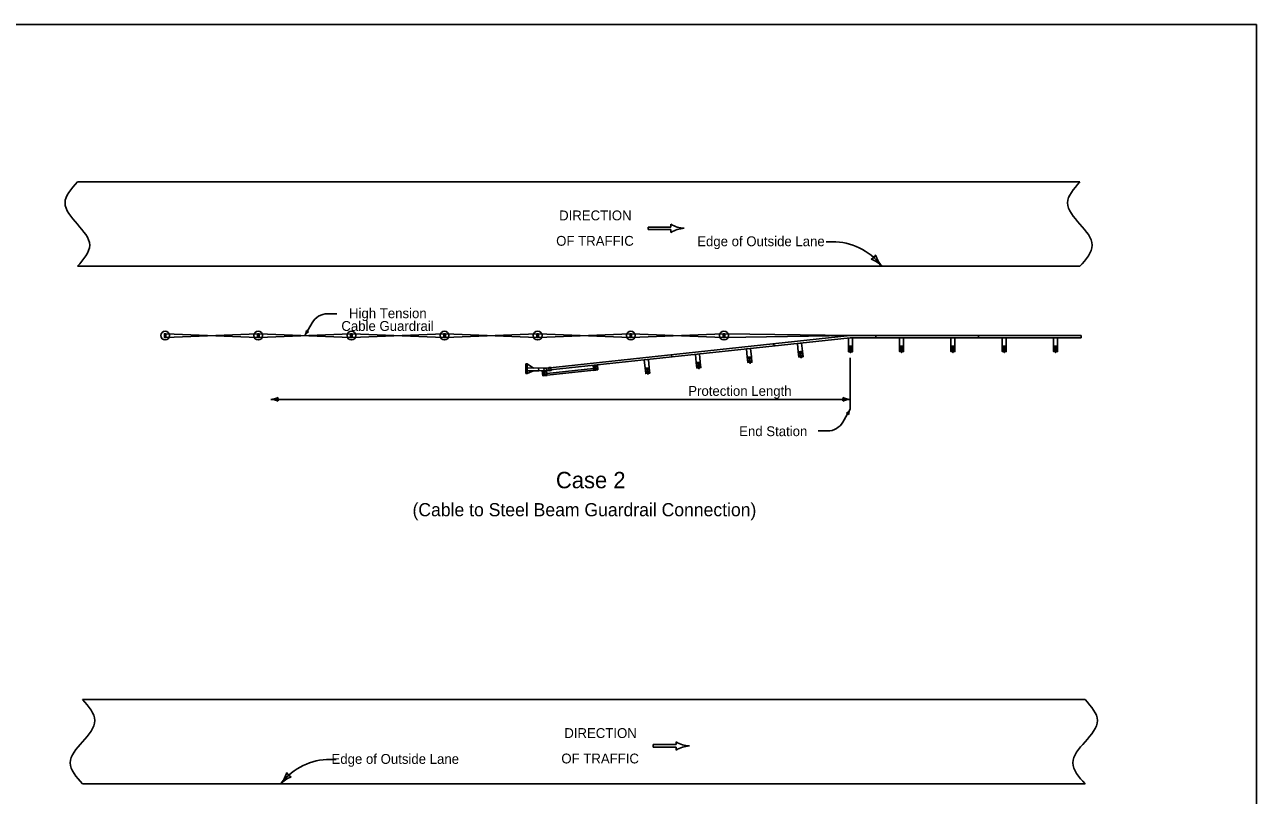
# Model space of a CAD drawing. Extents: x 10133 to 81668, y 7924 to 11018.
# Drawn here: x 22568 to 24068, y 9005 to 9944 of the extents above; entities that cross this region are included whole.
import ezdxf

# ---------------------------------------------------------------- set-up
doc = ezdxf.new("R2010")
doc.units = 0
for name, color, linetype in [('dsnCellElements', 7, 'Continuous'), ('DsnShtRevisedText', 7, 'Continuous'), ('dsnStdDimension', 7, 'Continuous'), ('Level 2', 7, 'Continuous'), ('Level 8', 7, 'Continuous'), ('SheetBorder', 7, 'Continuous')]:
    doc.layers.add(name, color=color, linetype=linetype)

msp = doc.modelspace()

# ---------------------------------------------------------------- linework, layer by layer
at = {"layer": 'dsnCellElements'}
for p, q in [((22851.5, 9562.9), (22740, 9567.4)), ((22851.5, 9567.4), (22740, 9562.9)), ((22964.9, 9562.9), (22853.4, 9567.4)), ((22964.9, 9567.4), (22853.4, 9562.9)), ((23078.3, 9562.9), (22966.8, 9567.4)), ((23078.3, 9567.4), (22966.8, 9562.9)), ((23191.7, 9562.9), (23080.2, 9567.4)), ((23191.7, 9567.4), (23080.2, 9562.9)), ((23305.1, 9562.9), (23193.6, 9567.4)), ((23305.1, 9567.4), (23193.6, 9562.9)), ((23418.5, 9562.9), (23307, 9567.4)), ((23418.5, 9567.4), (23307, 9562.9)), ((23420.4, 9567.5), (23573.1, 9565.2)), ((23420.4, 9562.9), (23573.1, 9565.2))]:
    msp.add_line(p, q, dxfattribs=at)
for points in [[(22740, 9567.4), (22740, 9562.9), (22738.1, 9562.9), (22738.1, 9567.4)], [(22853.4, 9567.4), (22853.4, 9562.9), (22851.5, 9562.9), (22851.5, 9567.4)], [(22853.4, 9567.4), (22853.4, 9562.9), (22851.5, 9562.9), (22851.5, 9567.4)], [(22966.8, 9567.4), (22966.8, 9562.9), (22964.9, 9562.9), (22964.9, 9567.4)], [(22966.8, 9567.4), (22966.8, 9562.9), (22964.9, 9562.9), (22964.9, 9567.4)], [(23080.2, 9567.4), (23080.2, 9562.9), (23078.3, 9562.9), (23078.3, 9567.4)], [(23080.2, 9567.4), (23080.2, 9562.9), (23078.3, 9562.9), (23078.3, 9567.4)], [(23193.6, 9567.4), (23193.6, 9562.9), (23191.7, 9562.9), (23191.7, 9567.4)], [(23193.6, 9567.4), (23193.6, 9562.9), (23191.7, 9562.9), (23191.7, 9567.4)], [(23307, 9567.4), (23307, 9562.9), (23305.1, 9562.9), (23305.1, 9567.4)], [(23307, 9567.4), (23307, 9562.9), (23305.1, 9562.9), (23305.1, 9567.4)], [(23420.4, 9567.4), (23420.4, 9562.9), (23418.5, 9562.9), (23418.5, 9567.4)]]:
    msp.add_lwpolyline(points, close=True, dxfattribs=at)
for centre in [(22739, 9565.2), (22852.4, 9565.2), (22852.4, 9565.2), (22965.8, 9565.2), (22965.8, 9565.2), (23079.2, 9565.2), (23079.2, 9565.2), (23192.6, 9565.2), (23192.6, 9565.2), (23306, 9565.2), (23306, 9565.2), (23419.4, 9565.2)]:
    msp.add_circle(centre, 5.32, dxfattribs=at)
at = {"layer": 'DsnShtRevisedText'}
for p, q in [((23354.8, 9697.4), (23326.9, 9697.4)), ((23326.9, 9697.4), (23326.9, 9694.4)), ((23326.9, 9694.4), (23354.8, 9694.4)), ((23354.8, 9701), (23354.8, 9697.4)), ((23354.8, 9694.4), (23354.8, 9690.8)), ((23371, 9695.9), (23371, 9695.9)), ((23543.9, 9679.5), (23551.3, 9679.5)), ((22936.8, 9591.6), (22948.1, 9591.6)), ((22918, 9580.8), (22909.1, 9565.2)), ((23573.1, 9538.1), (23573.1, 9475.5)), ((23550.6, 9487.5), (22867.6, 9487.5)), ((23573.1, 9487.5), (23550.6, 9487.5)), ((23564.2, 9459.8), (23573.1, 9475.5)), ((23545.4, 9449), (23534.1, 9449)), ((23361.1, 9066.9), (23333.1, 9066.9)), ((23333.1, 9066.9), (23333.1, 9063.8)), ((23333.1, 9063.8), (23361.1, 9063.8)), ((23361.1, 9070.4), (23361.1, 9066.9)), ((23361.1, 9063.8), (23361.1, 9060.2)), ((23377.3, 9065.3), (23377.3, 9065.3)), ((22947.4, 9048.9), (22939.9, 9048.9))]:
    msp.add_line(p, q, dxfattribs=at)
for centre, radius, start, end in [((23372.3, 9728.6), 32.7, 237.618, 267.648), ((23372.3, 9663.2), 32.7, 92.352, 122.382), ((23551.3, 9603.3), 76.2, 39.0106, 90), ((23593.3, 9669.5), 12.5, 295.2639, 330.7306), ((23588.1, 9627.5), 32.4, 42.9973, 71.0698), ((23635.5, 9671.7), 32.4, 194.9248, 222.9973), ((22936.8, 9569.9), 21.8, 90, 149.7757), ((22897.4, 9572), 13.6, 329.7686, 357.8411), ((22920.9, 9558.3), 13.6, 121.6962, 149.7686), ((22914.9, 9575), 5.25, 222.0353, 257.502), ((22867.6, 9506.6), 19.1, 270, 298.0725), ((22867.6, 9468.3), 19.1, 61.9275, 90), ((22883.6, 9487.5), 7.39, 162.2666, 197.7334), ((23557, 9487.5), 7.39, 342.2666, 17.7333), ((23573.1, 9506.6), 19.1, 241.9275, 270), ((23573.1, 9468.3), 19.1, 90, 118.0725), ((23561.3, 9482.3), 13.6, 301.6962, 329.7686), ((23567.3, 9465.6), 5.25, 42.0353, 77.502), ((23584.8, 9468.6), 13.6, 149.7686, 177.8411), ((23545.4, 9470.8), 21.8, 270, 329.7757), ((23378.6, 9098), 32.7, 237.618, 267.648), ((23378.6, 9032.6), 32.7, 92.352, 122.382), ((22939.9, 8972.7), 76.2, 90, 140.9894), ((22855.7, 9041.1), 32.4, 317.0027, 345.0752), ((22903.1, 8996.9), 32.4, 108.9302, 137.0027), ((22897.9, 9038.9), 12.5, 209.2694, 244.7361)]:
    msp.add_arc(centre, radius, start, end, dxfattribs=at)
at = {"layer": 'dsnStdDimension'}
for p, q in [((23852.7, 9752.5), (22632.2, 9752.5)), ((23852.7, 9649.6), (22632.2, 9649.6)), ((22638.5, 9121.9), (23859, 9121.9)), ((22638.5, 9019), (23859, 9019))]:
    msp.add_line(p, q, dxfattribs=at)
for points in [[(22632.2, 9752.5), (22617.2, 9726.8), (22632.2, 9701), (22647.2, 9675.3), (22632.2, 9649.6)], [(23852.7, 9752.5), (23837.7, 9726.8), (23852.7, 9701), (23867.7, 9675.3), (23852.7, 9649.6)], [(22638.5, 9121.9), (22653.5, 9096.2), (22638.5, 9070.5), (22623.5, 9044.7), (22638.5, 9019)], [(23859, 9121.9), (23874, 9096.2), (23859, 9070.5), (23844, 9044.7), (23859, 9019)]]:
    msp.add_spline(points, degree=3, dxfattribs=at)
at = {"layer": 'Level 2'}
for p, q in [((23200.2, 9525.2), (23573.1, 9565.2)), ((23200.5, 9522.5), (23573.1, 9562.5)), ((23480, 9555.2), (23480.3, 9552.5)), ((23571, 9562.2), (23576, 9562.5)), ((23571, 9552.2), (23571, 9562.2)), ((23576, 9552.2), (23571, 9552.2)), ((23576, 9545.6), (23571, 9552.2)), ((23571, 9545.6), (23576, 9552.2)), ((23573.1, 9565.2), (23604.4, 9565.2)), ((23573.1, 9562.5), (23604.4, 9562.5)), ((23573.5, 9552.2), (23573.5, 9545.6)), ((23576, 9562.5), (23576, 9552.2)), ((23604.4, 9565.2), (23604.4, 9562.5)), ((23729.4, 9565.2), (23604.4, 9565.2)), ((23604.4, 9565.2), (23604.4, 9562.5)), ((23729.4, 9562.5), (23604.4, 9562.5)), ((23633.1, 9552.4), (23633.1, 9562.5)), ((23633.1, 9562.5), (23638.1, 9562.5)), ((23638.1, 9552.4), (23633.1, 9552.4)), ((23638.1, 9545.8), (23633.1, 9552.4)), ((23633.1, 9545.8), (23638.1, 9552.4)), ((23635.6, 9552.4), (23635.6, 9545.8)), ((23638.1, 9562.5), (23638.1, 9552.4)), ((23695.6, 9552.4), (23695.6, 9562.5)), ((23695.6, 9562.5), (23700.6, 9562.5)), ((23700.6, 9552.4), (23695.6, 9552.4)), ((23700.6, 9545.8), (23695.6, 9552.4)), ((23695.6, 9545.8), (23700.6, 9552.4)), ((23698.1, 9552.4), (23698.1, 9545.8)), ((23700.6, 9562.5), (23700.6, 9552.4)), ((23729.4, 9565.2), (23729.4, 9562.5)), ((23854.4, 9565.2), (23729.4, 9565.2)), ((23729.4, 9565.2), (23729.4, 9562.5)), ((23854.4, 9562.5), (23729.4, 9562.5)), ((23758.1, 9552.4), (23758.1, 9562.5)), ((23758.1, 9562.5), (23763.1, 9562.5)), ((23763.1, 9552.4), (23758.1, 9552.4)), ((23763.1, 9545.8), (23758.1, 9552.4)), ((23758.1, 9545.8), (23763.1, 9552.4)), ((23760.6, 9552.4), (23760.6, 9545.8)), ((23763.1, 9562.5), (23763.1, 9552.4)), ((23820.6, 9552.4), (23820.6, 9562.5)), ((23820.6, 9562.5), (23825.6, 9562.5)), ((23825.6, 9552.4), (23820.6, 9552.4)), ((23825.6, 9545.8), (23820.6, 9552.4)), ((23820.6, 9545.8), (23825.6, 9552.4)), ((23823.1, 9552.4), (23823.1, 9545.8)), ((23825.6, 9562.5), (23825.6, 9552.4)), ((23854.4, 9565.2), (23854.4, 9562.5)), ((23355.7, 9541.8), (23356, 9539.2)), ((23453.5, 9532.8), (23447.8, 9538.9)), ((23448.5, 9532.3), (23452.8, 9539.5)), ((23450.3, 9539.2), (23451, 9532.6)), ((23515.6, 9539.5), (23509.9, 9545.6)), ((23510.6, 9539), (23514.9, 9546.1)), ((23512.4, 9545.9), (23513.1, 9539.2)), ((23513.2, 9538.3), (23513.2, 9538.2)), ((23635.6, 9544.8), (23635.6, 9544.7)), ((23698.1, 9544.8), (23698.1, 9544.7)), ((23760.6, 9544.8), (23760.6, 9544.7)), ((23823.1, 9544.8), (23823.1, 9544.7)), ((23193.7, 9525.5), (23206.3, 9526)), ((23206.4, 9522.8), (23193.8, 9522.3)), ((23199.1, 9522.3), (23199.1, 9522.2)), ((23200.2, 9525.2), (23200.5, 9522.5)), ((23200.6, 9522.3), (23201.3, 9516.5)), ((23203.5, 9525.9), (23203.6, 9522.7)), ((23204, 9516.9), (23260.8, 9523)), ((23261.5, 9529), (23265.2, 9529.4)), ((23262.8, 9529.2), (23263.4, 9523.2)), ((23329.2, 9519.5), (23323.5, 9525.6)), ((23324.2, 9519), (23328.5, 9526.1)), ((23326, 9525.9), (23326.7, 9519.2)), ((23391.3, 9526.2), (23385.6, 9532.3)), ((23386.4, 9525.6), (23390.6, 9532.8)), ((23388.1, 9532.5), (23388.8, 9525.9)), ((23388.9, 9524.9), (23389, 9524.9)), ((23451.1, 9531.6), (23451.1, 9531.5)), ((23451.4, 9532.6), (23451.5, 9532.5)), ((23326.8, 9518.3), (23326.8, 9518.2))]:
    msp.add_line(p, q, dxfattribs=at)
for points in [[(23513.8, 9556.1), (23508.9, 9555.6), (23509.9, 9545.6), (23514.9, 9546.1)], [(23576, 9552.2), (23571, 9552.2), (23571, 9545.6), (23576, 9545.6)], [(23638.1, 9552.4), (23633.1, 9552.4), (23633.1, 9545.8), (23638.1, 9545.8)], [(23700.6, 9552.4), (23695.6, 9552.4), (23695.6, 9545.8), (23700.6, 9545.8)], [(23763.1, 9552.4), (23758.1, 9552.4), (23758.1, 9545.8), (23763.1, 9545.8)], [(23825.6, 9552.4), (23820.6, 9552.4), (23820.6, 9545.8), (23825.6, 9545.8)], [(23389.5, 9542.8), (23384.6, 9542.2), (23385.6, 9532.3), (23390.6, 9532.8)], [(23451.7, 9549.4), (23446.7, 9548.9), (23447.8, 9538.9), (23452.8, 9539.5)], [(23452.8, 9539.5), (23447.8, 9538.9), (23448.5, 9532.3), (23453.5, 9532.8)], [(23514.9, 9546.1), (23509.9, 9545.6), (23510.6, 9539), (23515.6, 9539.5)], [(23206.4, 9522.7), (23206.5, 9522.4), (23209, 9522.5), (23208.9, 9522.8), (23208.8, 9526.2), (23208.8, 9526.5), (23206.3, 9526.4), (23206.3, 9526.1)], [(23327.4, 9536.1), (23322.4, 9535.6), (23323.5, 9525.6), (23328.5, 9526.1)], [(23328.5, 9526.1), (23323.5, 9525.6), (23324.2, 9519), (23329.2, 9519.5)], [(23390.6, 9532.8), (23385.6, 9532.3), (23386.4, 9525.6), (23391.3, 9526.2)]]:
    msp.add_lwpolyline(points, close=True, dxfattribs=at)
for points in [[(23513.5, 9539.3), (23513.5, 9538.9), (23512.8, 9538.8), (23512.8, 9539.2)], [(23513.4, 9538.8), (23513.4, 9538.3), (23513, 9538.3), (23513, 9538.8)], [(23573.8, 9545.6), (23573.8, 9545.2), (23573.2, 9545.2), (23573.2, 9545.6)], [(23573.7, 9545.2), (23573.7, 9544.6), (23573.3, 9544.6), (23573.3, 9545.2)], [(23636, 9545.8), (23636, 9545.3), (23635.3, 9545.3), (23635.3, 9545.8)], [(23635.8, 9545.3), (23635.8, 9544.8), (23635.4, 9544.8), (23635.4, 9545.3)], [(23698.5, 9545.8), (23698.5, 9545.3), (23697.8, 9545.3), (23697.8, 9545.8)], [(23698.3, 9545.3), (23698.3, 9544.8), (23697.9, 9544.8), (23697.9, 9545.3)], [(23761, 9545.8), (23761, 9545.3), (23760.3, 9545.3), (23760.3, 9545.8)], [(23760.8, 9545.3), (23760.8, 9544.8), (23760.4, 9544.8), (23760.4, 9545.3)], [(23823.5, 9545.8), (23823.5, 9545.3), (23822.8, 9545.3), (23822.8, 9545.8)], [(23823.3, 9545.3), (23823.3, 9544.8), (23822.9, 9544.8), (23822.9, 9545.3)], [(23178.1, 9518.9), (23178.3, 9530.6)], [(23178.3, 9530.5), (23179.8, 9530.5), (23179.7, 9519), (23178.1, 9519.1)], [(23179.9, 9530.6), (23178.3, 9530.6)], [(23179.9, 9530.6), (23179.8, 9518.9)], [(23193.8, 9522.2), (23179.8, 9522.4)], [(23187.4, 9522.3), (23179.8, 9518.9)], [(23187.3, 9525.7), (23179.9, 9530.6)], [(23193.7, 9525.6), (23179.9, 9525.8)], [(23206.4, 9522.7), (23193.8, 9522.2), (23193.7, 9525.6), (23206.3, 9526.1)], [(23198.2, 9522.1), (23203.1, 9522.6)], [(23198.2, 9522.1), (23203.8, 9516.8)], [(23198.2, 9522.1), (23198.8, 9516.3)], [(23203.1, 9522.6), (23198.8, 9516.3)], [(23203.1, 9522.7), (23199.1, 9522.3)], [(23203.1, 9522.6), (23199.1, 9522.2)], [(23203.2, 9522.5), (23203.2, 9522.1)], [(23203.2, 9522.1), (23203.3, 9521.9)], [(23203.4, 9522.6), (23203.4, 9522.2)], [(23203.4, 9522.2), (23203.4, 9522)], [(23203.7, 9518.9), (23260.5, 9525)], [(23203.8, 9518.9), (23260.5, 9525)], [(23204, 9516.9), (23260.8, 9523)], [(23206.3, 9526.1), (23208.8, 9526.2), (23208.9, 9522.8), (23206.4, 9522.7)], [(23260.1, 9528.7), (23260.2, 9528.3)], [(23260.2, 9528.3), (23260.8, 9523)], [(23260.3, 9528.9), (23265.3, 9529.4)], [(23260.3, 9528.7), (23265.3, 9529.3)], [(23260.3, 9528.7), (23265.9, 9523.5)], [(23260.3, 9528.7), (23260.3, 9528.3)], [(23260.3, 9528.3), (23260.9, 9522.9)], [(23265.3, 9529.3), (23260.9, 9522.9)], [(23260.9, 9522.9), (23265.9, 9523.5)], [(23261, 9522.8), (23265.9, 9523.3)], [(23265.3, 9529.4), (23265.9, 9523.3)], [(23389.2, 9525.9), (23389.2, 9525.5), (23388.6, 9525.4), (23388.5, 9525.9)], [(23389.1, 9525.5), (23389.1, 9525), (23388.8, 9524.9), (23388.7, 9525.5)], [(23451.3, 9532.6), (23451.4, 9532.2), (23450.7, 9532.1), (23450.7, 9532.5)], [(23451.2, 9532.2), (23451.3, 9531.6), (23450.9, 9531.6), (23450.8, 9532.1)], [(23179.8, 9518.9), (23178.1, 9518.9)], [(23198.8, 9516.3), (23203.8, 9516.8)], [(23203.8, 9516.8), (23199.7, 9516.4)], [(23203.8, 9516.6), (23199.7, 9516.2)], [(23199.7, 9516.2), (23199.7, 9516.4)], [(23203.3, 9521.9), (23203.6, 9519.1)], [(23203.4, 9522), (23203.7, 9519.1)], [(23203.6, 9519.1), (23203.8, 9516.8)], [(23203.7, 9519.1), (23204, 9516.9)], [(23327, 9519.3), (23327.1, 9518.8), (23326.4, 9518.8), (23326.4, 9519.2)], [(23326.9, 9518.8), (23327, 9518.3), (23326.6, 9518.3), (23326.6, 9518.8)]]:
    msp.add_lwpolyline(points, dxfattribs=at)
for centre, radius, start, end in [((23203.2, 9522.5), 0.208, 6.1292, 96.1292), ((23203.2, 9522.5), 0.0517, 6.1292, 96.1292), ((23260.4, 9528.7), 0.208, 96.1292, 186.1292), ((23261, 9523), 0.208, 186.1292, 276.1292), ((23203.8, 9516.8), 0.208, 276.1292, 6.1292), ((23203.8, 9516.8), 0.0517, 276.1292, 6.1292)]:
    msp.add_arc(centre, radius, start, end, dxfattribs=at)
at = {"layer": 'SheetBorder'}
msp.add_lwpolyline([(20932.5, 9944), (24067.5, 9944), (24067.5, 7924), (20932.5, 7924)], close=True, dxfattribs=at)

# ---------------------------------------------------------------- texts
at = {"layer": 'DsnShtRevisedText'}
for s, p in [('DIRECTION', (23218.7, 9705.6)), ('OF TRAFFIC', (23215.1, 9674.6)), ('Edge of Outside Lane', (23386.8, 9674.1)), ('High Tension', (22962.9, 9586.4)), ('Cable Guardrail', (22953.6, 9570.9)), ('Protection Length', (23375.9, 9491.8)), ('End Station', (23437.9, 9442.7)), ('DIRECTION', (23225, 9075)), ('Edge of Outside Lane', (22941.6, 9043.5)), ('OF TRAFFIC', (23221.4, 9044))]:
    msp.add_text(s, height=12, dxfattribs=at).set_placement(p)
at = {"layer": 'Level 8'}
for s, height, p in [('Case 2', 20, (23214.8, 9379.2)), ('(Cable to Steel Beam Guardrail Connection)', 16, (23040.2, 9345.1))]:
    msp.add_text(s, height=height, dxfattribs=at).set_placement(p)

doc.saveas('drawing.dxf')
